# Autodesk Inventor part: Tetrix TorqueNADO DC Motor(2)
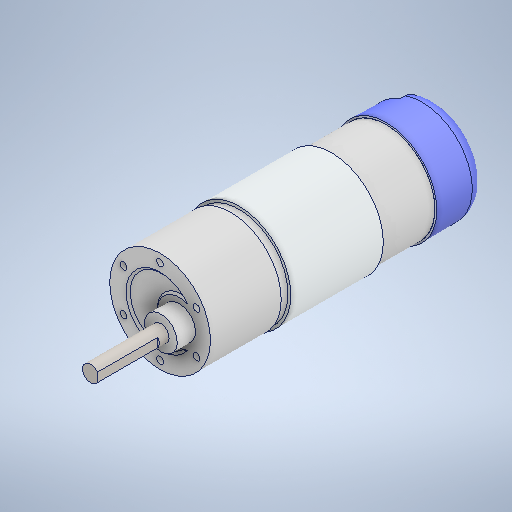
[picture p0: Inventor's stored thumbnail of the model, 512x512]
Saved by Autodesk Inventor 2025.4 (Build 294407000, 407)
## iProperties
Created: 2021-10
Part Number: Tetrix TorqueNADO DC Motor(2)
Material: Genérico
Document SubType Name: Modeling
Designer: usuario
Density: 1 g/cm^3
Appearance: Valor por defecto
Author: usuario
Sending System: SolidWorks 2016
Last Author: LENOVO
Last Saved: 2021-10-26
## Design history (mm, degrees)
feature "JST 4-pin receptacle PCB-1-solid1"
feature "Boss-Extrude1"
node "Sólido1"
node "Sólido2"
